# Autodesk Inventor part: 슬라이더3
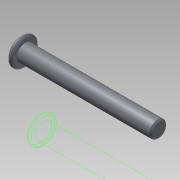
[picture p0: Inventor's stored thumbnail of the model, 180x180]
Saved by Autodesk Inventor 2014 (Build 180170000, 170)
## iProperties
Company: 한국ATC센터
Created: 2015-04
Part Number: 슬라이더3
Document SubType Name: Modeling
Designer: KYOUNG IL JANG
Density: 7.85 g/cm^3
Material: 강
Mass: 92.8999 g
Surface Area: 43.7403 cm^2
Volume: 11.8344 cm^3
Appearance: 강철
Author: KYOUNG IL JANG
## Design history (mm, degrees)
sketch "스케치1"
  geometry: L1 (0, 0)-(0, 10); L2 (0, 10)-(-3, 10); L3 (-3, 10)-(-3, 6); L4 (-3, 6)-(-100, 6); L5 (-100, 6)-(-100, 0); L6 (-100, 0)-(0, 0)
  constraints: 12 end point, 4 parallel, 1 perpendicular, 1 vertical
  dimensions: "d0" = 12 diameter of L4 L6; "d1" = 20 diameter of L2 L6; "d2" = 3 distance between parallel lines of L3 L1; "d3" = 100 distance between parallel lines of L5 L1
revolve "회전1" sketch "스케치1" stored, may be unused: angle "d4" = 90 deg
chamfer "모따기1" distance "d5" = 1; stored, may be unused: second distance "d6" = 2, angle "d7" = 45 deg
node "솔리드1"
